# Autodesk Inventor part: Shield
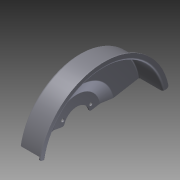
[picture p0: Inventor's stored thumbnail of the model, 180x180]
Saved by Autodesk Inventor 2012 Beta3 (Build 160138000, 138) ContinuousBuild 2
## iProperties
Created: 2010-12
Part Number: Shield
Material: Steel
Document SubType Name: Sheet Metal
Designer: Thom Tremblay
Density: 7.85 g/cm^3
Sheet Metal Rule: 16ga Steel
Sheet Metal Width: 0.000 mm
Sheet Metal Length: 0.000 mm
Sheet Metal Area: 0.000 mm^2
Author: Thom Tremblay
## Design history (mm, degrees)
sketch "Sketch1"
  geometry: L1 (0, 0)-(52.833, 0); L2 (0, 18)-(0, 32.5); L3 (0, 32.5)-(5, 46.237); L4 (5, 46.237)-(5, 82.5); L5 (5, 82.5)-(38, 82.5); L6 (38, 82.5)-(38, 90.5)
  constraints: 12 end point, 2 parallel, 2 perpendicular, 1 horizontal, 1 point on line
  dimensions: "d0" = 165 diameter of L5 L1; "d1" = 33 distance of L4.end L5.end; "d3" = 36 diameter of L2.start L1; "d4" = 65 diameter of L2.end L1; "d6" = 38 distance between parallel lines of L6 L2 (derived); "d23" = 5 horizontal distance of L2.end L3.end; "d24" = 20 deg angle of L2 L3; "d25" = 8 distance of L5.end L6.end
feature "Contour Roll1" sketch "Sketch1" dims "d9" = 160 deg, "d10" = 175.23857, "d11" = 62.75269, "Thickness" = 1.524 (derived)
sketch "Sketch2"
  geometry: L1 (0, 0)-(-19.486, 11.25); L2 (19.486, 11.25)-(0, 0); L3 (0, 0)-(0, 22.5); A1 r 22.5 centre (0, 0) between (19.486, 11.25) and (-19.486, 11.25)
  constraints: 6 end point, 3 point on circle, 1 centre point, 1 vertical
  dimensions: "d12" = 22.5 radius of A1; "d13" = 120 deg angle of L1 L2; "d14" = 60 deg angle of L1 L3 (= 0.5 x d13)
hole "Hole1" sketch "Sketch2" at (-19.486, 11.25), (19.486, 11.25) diameter "d15" = 4.4958; stored, may be unused: countersink angle "d19" = 82 deg, drill point angle "d21" = 118 deg; dims "d16" = 19.05, "d17" = 8.4328, "d18" = 6.35, "d20" = 1.524 (= Thickness)
feature "Corner Round1" dims "d22" = 2.54
body "Solid1"
other parameters: "BendRadius" = 1.524 (= Thickness), "BendReliefWidth" = 1.524 (= Thickness), "BendReliefDepth" = 0.762 (= 0.5 x Thickness), "CornerReliefSize" = 6.096 (= 4 x Thickness), "SeamGap" = 0.00508, "MinimumRemnant" = 3.048 (= 2 x Thickness), "TransitionRadius" = 1.524 (= BendRadius), "JacobiRadiusSize" = 1.524 (= BendRadius), "GapSize" = 1.524 (= Thickness), "d8" = 1.524 (= BendRadius)
